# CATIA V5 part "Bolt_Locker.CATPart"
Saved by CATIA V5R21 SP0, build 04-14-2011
Part number: Bolt_Holder.1
Bounding box of the stored display mesh (mm): x -89 to 89, y -7 to 7, z 0 to 2.8
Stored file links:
  C:\Users\Pouria\Desktop\Box\Assembled\Bolt_Locker.CATPart
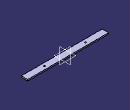
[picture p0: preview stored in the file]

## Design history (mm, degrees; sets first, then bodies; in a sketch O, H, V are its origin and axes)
Body1 (main body)
  Sketch1 on xy-plane, origin (0, 0, 0), H (1, 0, 0), V (0, 1, 0)
    line L1 (89, 7) -> (89, -7)
    line L2 (89, -7) -> (-89, -7)
    line L3 (-89, -7) -> (-89, 7)
    line L4 (-89, 7) -> (89, 7)
    circle A1 centre (45, 0) radius 1.5
    point P5 (45, 0)
    circle A2 centre (-45, 0) radius 1.5
    point P6 (-45, 0)
    length L4 = 178
    length L1 = 14
    distance P6 L3 = 44
    distance P5 L1 = 44
    radius A1 = 1.5
    radius A2 = 1.5
    vertical: L1 V, L3 V
    horizontal: L2 H, L4 H
    equidistance: L1 L3 O, L2 L4 O
    coincidence: P5 H, P6 H
  Pad1: profile Sketch1, direction (0, 0, 1), length 2.8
